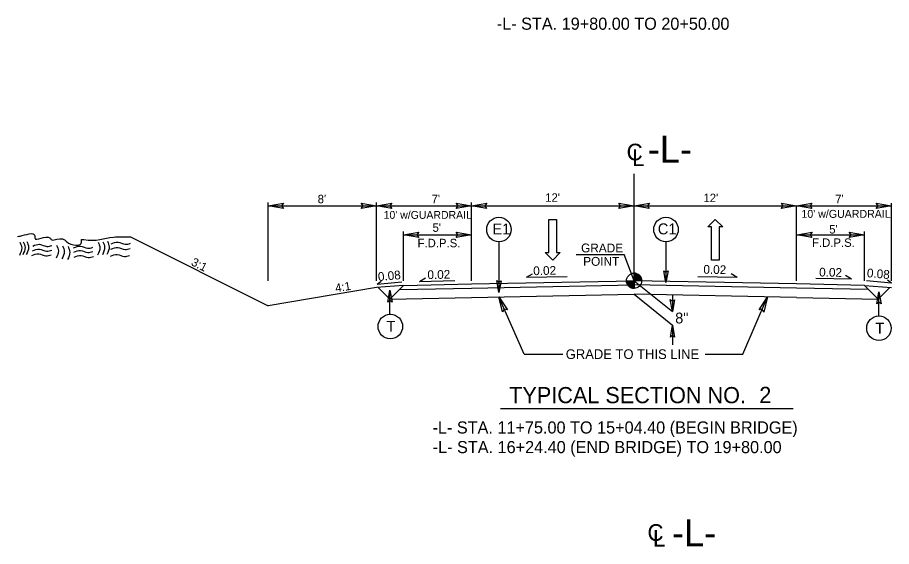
# Model space of a CAD drawing. Extents: x 1733676 to 1734289, y 540979 to 541226.
# Drawn here: x 1734171.6 to 1734236.1, y 541147.3 to 541186.4 of the extents above; entities that cross this region are included whole.
import ezdxf

# ---------------------------------------------------------------- set-up
doc = ezdxf.new("R2010")
doc.units = 0
for name, color, linetype in [('Old_Level_2', 7, 'Continuous'), ('Prop Dimension', 7, 'Continuous'), ('Prop Lane Arrow CELL', 7, 'Continuous'), ('Prop Terminator CELL', 7, 'Continuous'), ('Typical Grade Point Symbol CELL', 7, 'Continuous'), ('Typical ID Circle CELL', 7, 'Continuous'), ('Typical Pavement Slope CELL', 7, 'Continuous'), ('Typical Pavement Slope Information CELL', 7, 'Continuous'), ('Typical Shoulder Slope CELL', 7, 'Continuous'), ('Typical Shoulder Slope Information CELL', 7, 'Continuous'), ('Typical Slope Point Local CELL', 7, 'Continuous'), ('Typical Terminator CELL', 7, 'Continuous'), ('Typical Text Centerline CELL', 7, 'Continuous'), ('Typical Text General CELL', 7, 'Continuous'), ('Typical Text Grade Point CELL', 7, 'Continuous'), ('Typical Text ID Circle CELL', 7, 'Continuous'), ('Typical Text Label CELL', 7, 'Continuous')]:
    doc.layers.add(name, color=color, linetype=linetype)

msp = doc.modelspace()

# ---------------------------------------------------------------- linework, layer by layer
at = {"layer": 'Old_Level_2'}
for points in [[(1734171.638, 541170.263), (1734171.824, 541170.285), (1734172.92, 541170.298), (1734172.922, 541170.141), (1734174.019, 541170.154), (1734174.177, 541169.999), (1734174.334, 541170.001), (1734175.117, 541170.01), (1734175.275, 541169.855), (1734176.372, 541169.868), (1734176.37, 541170.024), (1734176.526, 541170.026), (1734178.717, 541170.208), (1734179.966, 541170.223)], [(1734171.821, 541169.824), (1734171.948, 541169.404), (1734171.779, 541168.858)], [(1734172.066, 541169.862), (1734172.194, 541169.442), (1734172.024, 541168.896)], [(1734172.329, 541169.882), (1734172.456, 541169.463), (1734172.287, 541168.917)], [(1734172.763, 541169.545), (1734173.27, 541169.674), (1734173.798, 541169.522), (1734174.183, 541169.597)], [(1734177.593, 541169.838), (1734177.72, 541169.418), (1734177.551, 541168.872)], [(1734177.943, 541169.86), (1734178.071, 541169.44), (1734177.902, 541168.894)], [(1734178.276, 541169.898), (1734178.404, 541169.479), (1734178.235, 541168.933)], [(1734178.551, 541169.7), (1734179.058, 541169.829), (1734179.586, 541169.677), (1734179.971, 541169.751)], [(1734172.749, 541169.194), (1734173.257, 541169.323), (1734173.785, 541169.171), (1734174.17, 541169.245)], [(1734174.525, 541169.609), (1734174.653, 541169.19), (1734174.484, 541168.644)], [(1734174.964, 541169.562), (1734175.092, 541169.142), (1734174.923, 541168.596)], [(1734175.368, 541169.514), (1734175.496, 541169.094), (1734175.327, 541168.548)], [(1734175.782, 541169.405), (1734176.289, 541169.533), (1734176.817, 541169.381), (1734177.203, 541169.456)], [(1734175.786, 541169.089), (1734176.293, 541169.217), (1734176.821, 541169.066), (1734177.206, 541169.14)], [(1734178.538, 541169.314), (1734179.045, 541169.442), (1734179.573, 541169.29), (1734179.958, 541169.365)], [(1734172.701, 541168.843), (1734173.208, 541168.971), (1734173.736, 541168.819), (1734174.121, 541168.894)], [(1734175.825, 541168.721), (1734176.332, 541168.849), (1734176.86, 541168.698), (1734177.246, 541168.772)], [(1734178.491, 541168.804), (1734178.998, 541168.933), (1734179.526, 541168.781), (1734179.912, 541168.856)]]:
    msp.add_spline(points, degree=3, dxfattribs=at)
at = {"layer": 'Prop Dimension'}
for p, q in [((1734217.135, 541166.983), (1734217.135, 541174.87)), ((1734190.135, 541166.983), (1734190.135, 541172.762)), ((1734190.135, 541172.512), (1734198.135, 541172.512)), ((1734198.135, 541166.983), (1734198.135, 541172.762)), ((1734198.135, 541172.512), (1734205.135, 541172.512)), ((1734205.135, 541166.983), (1734205.135, 541172.762)), ((1734205.135, 541172.512), (1734217.135, 541172.512)), ((1734217.135, 541172.512), (1734229.135, 541172.512)), ((1734229.135, 541166.983), (1734229.135, 541172.525)), ((1734229.135, 541172.512), (1734236.135, 541172.512)), ((1734236.135, 541166.983), (1734236.135, 541172.715)), ((1734200.13, 541166.983), (1734200.13, 541170.621)), ((1734200.13, 541170.371), (1734205.13, 541170.371)), ((1734229.139, 541170.371), (1734234.139, 541170.371)), ((1734234.139, 541166.983), (1734234.139, 541170.621)), ((1734212.862, 541168.921), (1734216.4, 541168.921)), ((1734217.135, 541166.983), (1734216.4, 541168.921)), ((1734217.135, 541166.983), (1734219.968, 541164.701)), ((1734217.135, 541165.983), (1734219.968, 541163.701)), ((1734219.968, 541165.907), (1734219.968, 541164.701)), ((1734225.162, 541161.561), (1734226.989, 541165.786)), ((1734209.026, 541161.561), (1734207.148, 541165.783)), ((1734219.968, 541163.701), (1734219.968, 541162.248)), ((1734209.026, 541161.561), (1734211.885, 541161.561)), ((1734222.385, 541161.561), (1734225.162, 541161.561))]:
    msp.add_line(p, q, dxfattribs=at)
at = {"layer": 'Prop Lane Arrow CELL'}
for p, q in [((1734210.838, 541169.058), (1734210.838, 541171.508)), ((1734210.838, 541171.508), (1734211.416, 541171.508)), ((1734211.416, 541171.508), (1734211.416, 541169.058)), ((1734222.583, 541170.956), (1734223.126, 541171.507)), ((1734222.846, 541170.956), (1734222.583, 541170.956)), ((1734222.846, 541168.506), (1734222.846, 541170.956)), ((1734223.126, 541171.507), (1734223.686, 541170.956)), ((1734223.686, 541170.956), (1734223.423, 541170.956)), ((1734223.423, 541170.956), (1734223.423, 541168.506)), ((1734211.136, 541168.507), (1734210.576, 541169.058)), ((1734210.576, 541169.058), (1734210.838, 541169.058)), ((1734211.678, 541169.058), (1734211.136, 541168.507)), ((1734211.416, 541169.058), (1734211.678, 541169.058)), ((1734223.423, 541168.506), (1734222.846, 541168.506))]:
    msp.add_line(p, q, dxfattribs=at)
at = {"layer": 'Prop Terminator CELL'}
for points in [[(1734191.26, 541172.318), (1734190.135, 541172.512), (1734191.266, 541172.712), (1734191.122, 541172.512)], [(1734197.01, 541172.706), (1734198.135, 541172.512), (1734197.003, 541172.312), (1734197.147, 541172.512)], [(1734199.26, 541172.318), (1734198.135, 541172.512), (1734199.266, 541172.712), (1734199.122, 541172.512)], [(1734204.01, 541172.706), (1734205.135, 541172.512), (1734204.003, 541172.312), (1734204.147, 541172.512)], [(1734206.26, 541172.318), (1734205.135, 541172.512), (1734206.266, 541172.712), (1734206.122, 541172.512)], [(1734216.01, 541172.706), (1734217.135, 541172.512), (1734216.003, 541172.312), (1734216.147, 541172.512)], [(1734218.26, 541172.318), (1734217.135, 541172.512), (1734218.266, 541172.712), (1734218.122, 541172.512)], [(1734228.01, 541172.706), (1734229.135, 541172.512), (1734228.003, 541172.312), (1734228.147, 541172.512)], [(1734230.26, 541172.318), (1734229.135, 541172.512), (1734230.266, 541172.712), (1734230.122, 541172.512)], [(1734235.01, 541172.706), (1734236.135, 541172.512), (1734235.003, 541172.312), (1734235.147, 541172.512)], [(1734201.255, 541170.177), (1734200.13, 541170.371), (1734201.262, 541170.571), (1734201.118, 541170.371)], [(1734204.005, 541170.565), (1734205.13, 541170.371), (1734203.999, 541170.171), (1734204.143, 541170.371)], [(1734230.264, 541170.177), (1734229.139, 541170.371), (1734230.27, 541170.571), (1734230.127, 541170.371)], [(1734233.014, 541170.565), (1734234.139, 541170.371), (1734233.008, 541170.171), (1734233.152, 541170.371)], [(1734226.365, 541164.83), (1734226.989, 541165.786), (1734226.724, 541164.668), (1734226.597, 541164.879)], [(1734207.428, 541164.677), (1734207.148, 541165.783), (1734207.79, 541164.831), (1734207.549, 541164.881)]]:
    msp.add_lwpolyline(points, close=True, dxfattribs=at)
at = {"layer": 'Typical Grade Point Symbol CELL'}
for p, q in [((1734217.135, 541166.983), (1734217.135, 541167.543)), ((1734216.575, 541166.983), (1734217.135, 541166.983)), ((1734217.133, 541166.424), (1734217.135, 541166.983)), ((1734217.135, 541166.983), (1734217.133, 541166.424)), ((1734217.694, 541166.983), (1734217.135, 541166.983))]:
    msp.add_line(p, q, dxfattribs=at)
for points in [[(1734217.14, 541167.543), (1734217.14, 541167.543), (1734217.14, 541166.983)], [(1734217.151, 541167.543), (1734217.151, 541166.983)], [(1734217.162, 541167.541), (1734217.162, 541166.983)], [(1734217.173, 541167.541), (1734217.173, 541166.983)], [(1734217.184, 541167.54), (1734217.184, 541166.983)], [(1734217.196, 541167.539), (1734217.196, 541166.983)], [(1734217.207, 541167.538), (1734217.207, 541166.983)], [(1734217.218, 541167.536), (1734217.218, 541166.983)], [(1734217.229, 541167.535), (1734217.229, 541166.983)], [(1734217.24, 541167.533), (1734217.24, 541166.983)], [(1734217.252, 541167.53), (1734217.252, 541166.983)], [(1734217.263, 541167.528), (1734217.263, 541166.983)], [(1734217.274, 541167.525), (1734217.274, 541166.983)], [(1734217.285, 541167.522), (1734217.285, 541166.983)], [(1734217.296, 541167.519), (1734217.296, 541166.983)], [(1734217.308, 541167.515), (1734217.308, 541166.983)], [(1734217.319, 541167.512), (1734217.319, 541166.983)], [(1734217.33, 541167.508), (1734217.33, 541166.983)], [(1734217.341, 541167.503), (1734217.341, 541166.983)], [(1734217.352, 541167.498), (1734217.352, 541166.983)], [(1734217.364, 541167.493), (1734217.364, 541166.983)], [(1734217.375, 541167.488), (1734217.375, 541166.983)], [(1734217.386, 541167.483), (1734217.386, 541166.983)], [(1734217.397, 541167.477), (1734217.397, 541166.983)], [(1734217.408, 541167.471), (1734217.408, 541166.983)], [(1734217.419, 541167.464), (1734217.419, 541166.983)], [(1734217.431, 541167.458), (1734217.431, 541166.983)], [(1734217.442, 541167.451), (1734217.442, 541166.983)], [(1734217.453, 541167.443), (1734217.453, 541166.983)], [(1734217.464, 541167.435), (1734217.464, 541166.983)], [(1734217.475, 541167.427), (1734217.475, 541166.983)], [(1734217.487, 541167.418), (1734217.487, 541166.983)], [(1734217.498, 541167.408), (1734217.498, 541166.983)], [(1734217.509, 541167.398), (1734217.509, 541166.983)], [(1734217.52, 541167.388), (1734217.52, 541166.983)], [(1734217.531, 541167.377), (1734217.531, 541166.983)], [(1734217.543, 541167.366), (1734217.543, 541166.983)], [(1734217.554, 541167.354), (1734217.554, 541166.983)], [(1734217.565, 541167.34), (1734217.565, 541166.983)], [(1734217.576, 541167.326), (1734217.576, 541166.983)], [(1734217.587, 541167.311), (1734217.587, 541166.983)], [(1734217.599, 541167.295), (1734217.599, 541166.983)], [(1734217.61, 541167.278), (1734217.61, 541166.983)], [(1734217.621, 541167.259), (1734217.621, 541166.983)], [(1734217.632, 541167.239), (1734217.632, 541166.983)], [(1734217.643, 541167.216), (1734217.643, 541166.983)], [(1734217.654, 541167.19), (1734217.654, 541166.983)], [(1734217.666, 541167.158), (1734217.666, 541166.983)], [(1734217.677, 541167.12), (1734217.677, 541166.983)], [(1734216.578, 541166.983), (1734216.578, 541166.922)], [(1734216.589, 541166.983), (1734216.589, 541166.856)], [(1734216.6, 541166.983), (1734216.6, 541166.817)], [(1734216.611, 541166.983), (1734216.611, 541166.783)], [(1734216.623, 541166.983), (1734216.623, 541166.757)], [(1734216.634, 541166.983), (1734216.634, 541166.733)], [(1734216.645, 541166.983), (1734216.645, 541166.712)], [(1734216.656, 541166.983), (1734216.656, 541166.692)], [(1734216.667, 541166.983), (1734216.667, 541166.675)], [(1734216.678, 541166.983), (1734216.678, 541166.659)], [(1734216.69, 541166.983), (1734216.69, 541166.644)], [(1734216.701, 541166.983), (1734216.701, 541166.63)], [(1734216.712, 541166.983), (1734216.712, 541166.616)], [(1734216.723, 541166.983), (1734216.723, 541166.604)], [(1734216.734, 541166.983), (1734216.734, 541166.592)], [(1734216.746, 541166.983), (1734216.746, 541166.58)], [(1734216.757, 541166.983), (1734216.757, 541166.57)], [(1734216.768, 541166.983), (1734216.768, 541166.56)], [(1734216.779, 541166.983), (1734216.779, 541166.551)], [(1734216.79, 541166.983), (1734216.79, 541166.542)], [(1734216.802, 541166.983), (1734216.802, 541166.533)], [(1734216.813, 541166.983), (1734216.813, 541166.526)], [(1734216.824, 541166.983), (1734216.824, 541166.518)], [(1734216.835, 541166.983), (1734216.835, 541166.511)], [(1734216.846, 541166.983), (1734216.846, 541166.503)], [(1734216.857, 541166.983), (1734216.857, 541166.497)], [(1734216.869, 541166.983), (1734216.869, 541166.491)], [(1734216.88, 541166.983), (1734216.88, 541166.485)], [(1734216.891, 541166.983), (1734216.891, 541166.48)], [(1734216.902, 541166.983), (1734216.902, 541166.475)], [(1734216.913, 541166.983), (1734216.913, 541166.47)], [(1734216.925, 541166.983), (1734216.925, 541166.465)], [(1734216.936, 541166.983), (1734216.936, 541166.46)], [(1734216.947, 541166.983), (1734216.947, 541166.456)], [(1734216.958, 541166.983), (1734216.958, 541166.452)], [(1734216.969, 541166.983), (1734216.969, 541166.449)], [(1734216.981, 541166.983), (1734216.981, 541166.446)], [(1734216.992, 541166.983), (1734216.992, 541166.442)], [(1734217.003, 541166.983), (1734217.003, 541166.44)], [(1734217.014, 541166.983), (1734217.014, 541166.437)], [(1734217.025, 541166.983), (1734217.025, 541166.435)], [(1734217.036, 541166.983), (1734217.036, 541166.432)], [(1734217.048, 541166.983), (1734217.048, 541166.431)], [(1734217.059, 541166.983), (1734217.059, 541166.429)], [(1734217.07, 541166.983), (1734217.07, 541166.427)], [(1734217.081, 541166.983), (1734217.081, 541166.426)], [(1734217.092, 541166.983), (1734217.092, 541166.425)], [(1734217.104, 541166.983), (1734217.104, 541166.425)], [(1734217.115, 541166.983), (1734217.115, 541166.424)], [(1734217.126, 541166.983), (1734217.126, 541166.424), (1734217.126, 541166.424)], [(1734217.688, 541167.063), (1734217.688, 541166.983)]]:
    msp.add_lwpolyline(points, dxfattribs=at)
msp.add_circle((1734217.134, 541166.983), 0.559, dxfattribs=at)
for start, end in [(359.99048, 89.99048), (179.99048, 269.99048)]:
    msp.add_arc((1734217.134, 541166.983), 0.559, start, end, dxfattribs=at)
at = {"layer": 'Typical ID Circle CELL'}
for p, q in [((1734207.168, 541169.861), (1734207.168, 541166.109)), ((1734219.493, 541169.861), (1734219.493, 541166.841)), ((1734199.12, 541164.507), (1734199.12, 541166.286)), ((1734235.208, 541164.384), (1734235.208, 541166.163))]:
    msp.add_line(p, q, dxfattribs=at)
for centre in [(1734207.168, 541170.767), (1734219.493, 541170.767), (1734199.152, 541163.601), (1734235.208, 541163.477)]:
    msp.add_circle(centre, 0.906, dxfattribs=at)
at = {"layer": 'Typical Pavement Slope CELL'}
for p, q in [((1734200.13, 541166.641), (1734198.13, 541166.474)), ((1734205.135, 541166.743), (1734217.135, 541166.983)), ((1734205.135, 541166.443), (1734217.141, 541166.683)), ((1734229.135, 541166.443), (1734217.129, 541166.683)), ((1734229.135, 541166.743), (1734217.135, 541166.983)), ((1734234.139, 541166.641), (1734236.14, 541166.474)), ((1734205.135, 541165.743), (1734217.135, 541165.983)), ((1734229.135, 541165.743), (1734217.135, 541165.983)), ((1734199.112, 541165.623), (1734205.135, 541165.743)), ((1734229.135, 541165.743), (1734235.157, 541165.623))]:
    msp.add_line(p, q, dxfattribs=at)
at = {"layer": 'Typical Pavement Slope Information CELL'}
for p, q in [((1734201.309, 541166.939), (1734201.747, 541167.203)), ((1734209.202, 541167.239), (1734209.639, 541167.504)), ((1734209.202, 541167.239), (1734212.193, 541167.299)), ((1734224.745, 541167.218), (1734221.851, 541167.276)), ((1734224.745, 541167.218), (1734224.296, 541167.49)), ((1734233.182, 541167.095), (1734230.542, 541167.148)), ((1734233.182, 541167.095), (1734232.733, 541167.366)), ((1734198.19, 541166.735), (1734198.482, 541166.94)), ((1734198.19, 541166.735), (1734199.999, 541166.896)), ((1734201.309, 541166.939), (1734203.909, 541166.991)), ((1734236.132, 541166.81), (1734234.294, 541166.965)), ((1734236.132, 541166.81), (1734235.831, 541167.019))]:
    msp.add_line(p, q, dxfattribs=at)
at = {"layer": 'Typical Shoulder Slope CELL'}
for p, q in [((1734198.25, 541166.484), (1734199.112, 541165.622)), ((1734200.13, 541166.641), (1734199.112, 541165.622)), ((1734199.824, 541166.334), (1734205.141, 541166.443)), ((1734200.13, 541166.641), (1734205.135, 541166.743)), ((1734234.445, 541166.334), (1734229.129, 541166.443)), ((1734234.139, 541166.641), (1734229.135, 541166.743)), ((1734234.139, 541166.641), (1734235.158, 541165.622)), ((1734236.02, 541166.484), (1734235.158, 541165.622))]:
    msp.add_line(p, q, dxfattribs=at)
at = {"layer": 'Typical Slope Point Local CELL'}
for p in [(1734179.966, 541170.223), (1734198.13, 541166.474)]:
    msp.add_line(p, (1734190.13, 541165.141), dxfattribs=at)
at = {"layer": 'Typical Terminator CELL'}
for points in [[(1734219.644, 541167.72), (1734219.493, 541166.841), (1734219.337, 541167.724), (1734219.493, 541167.612)], [(1734207.32, 541166.988), (1734207.168, 541166.109), (1734207.012, 541166.993), (1734207.168, 541166.88)], [(1734198.969, 541165.407), (1734199.12, 541166.286), (1734199.276, 541165.403), (1734199.12, 541165.515)], [(1734235.056, 541165.284), (1734235.208, 541166.163), (1734235.364, 541165.28), (1734235.208, 541165.392)], [(1734220.119, 541165.58), (1734219.968, 541164.701), (1734219.812, 541165.585), (1734219.968, 541165.472)], [(1734219.816, 541162.822), (1734219.968, 541163.701), (1734220.124, 541162.817), (1734219.968, 541162.929)]]:
    msp.add_lwpolyline(points, close=True, dxfattribs=at)
at = {"layer": 'Typical Text Label CELL'}
msp.add_line((1734207.283, 541157.537), (1734228.888, 541157.537), dxfattribs=at)

# ---------------------------------------------------------------- texts
at = {"layer": 'Typical Pavement Slope Information CELL'}
for rotation, p in [(1.14574, (1734209.703, 541167.394)), (358.85426, (1734222.248, 541167.503))]:
    msp.add_text('0.02', height=0.6476, rotation=rotation, dxfattribs=at).set_placement(p)
at = {"layer": 'Typical Shoulder Slope Information CELL'}
for s, rotation, p in [('0.08', 5.10489, (1734198.265, 541166.954)), ('0.02', 1.14574, (1734201.894, 541167.103)), ('0.02', 358.85426, (1734230.791, 541167.301)), ('0.08', 355.18719, (1734234.298, 541167.25))]:
    msp.add_text(s, height=0.6476, rotation=rotation, dxfattribs=at).set_placement(p)
at = {"layer": 'Typical Slope Point Local CELL'}
for s, height, rotation, p in [("8'", 0.6249, 360, (1734193.789, 541172.708)), ("7'", 0.6249, 360, (1734202.196, 541172.708)), ("12'", 0.6249, 360, (1734210.581, 541172.817)), ("12'", 0.6249, 360, (1734222.255, 541172.79)), ("7'", 0.6249, 360, (1734231.982, 541172.713)), ("10' w/GUARDRAIL", 0.58491, 360, (1734229.489, 541171.63)), ("10' w/GUARDRAIL", 0.57868, 360, (1734198.656, 541171.557)), ("5'", 0.6249, 360, (1734202.264, 541170.597)), ("5'", 0.6249, 360, (1734231.539, 541170.471)), ('F.D.P.S.', 0.6249, 360, (1734201.161, 541169.454)), ('F.D.P.S.', 0.6249, 360, (1734230.272, 541169.487)), ('3:1', 0.6249, 333.43495, (1734184.401, 541168.159)), ('4:1', 0.6249, 9.46232, (1734195.135, 541166.125)), ('8"', 0.8, 360, (1734220.172, 541163.828))]:
    msp.add_text(s, height=height, rotation=rotation, dxfattribs=at).set_placement(p)
at = {"layer": 'Typical Text Centerline CELL'}
for s, height, p in [('-L-', 2, (1734218.148, 541175.705)), ('C', 1.23, (1734216.586, 541175.875)), ('C', 1.23, (1734218.124, 541147.768)), ('-L-', 2, (1734219.93, 541147.367))]:
    msp.add_text(s, height=height, dxfattribs=at).set_placement(p)
for p in [(1734216.995, 541175.455), (1734218.533, 541147.348)]:
    msp.add_text('L', height=1.231, rotation=359.9469, dxfattribs=at).set_placement(p)
at = {"layer": 'Typical Text General CELL'}
msp.add_text('GRADE TO THIS LINE', height=0.71614, dxfattribs=at).set_placement((1734212.096, 541161.203))
at = {"layer": 'Typical Text Grade Point CELL'}
for s, p in [('GRADE', (1734213.226, 541169.077)), ('POINT', (1734213.383, 541168.088))]:
    msp.add_text(s, height=0.6525, dxfattribs=at).set_placement(p)
at = {"layer": 'Typical Text ID Circle CELL'}
for s, height, p in [('E1', 0.8112, (1734206.678, 541170.4)), ('C1', 0.8112, (1734218.888, 541170.408)), ('T', 0.811, (1734198.86, 541163.21)), ('T', 0.811, (1734234.941, 541163.072))]:
    msp.add_text(s, height=height, dxfattribs=at).set_placement(p)
at = {"layer": 'Typical Text Label CELL'}
for s, height, p in [('-L- STA. 19+80.00 TO 20+50.00', 0.89517, (1734207.007, 541185.524)), ('TYPICAL SECTION NO.  ', 1.19356, (1734207.924, 541157.937)), ('2', 1.194, (1734226.376, 541157.953)), ('-L- STA. 11+75.00 TO 15+04.40 (BEGIN BRIDGE)', 0.89517, (1734202.265, 541155.697)), ('-L- STA. 16+24.40 (END BRIDGE) TO 19+80.00', 0.89517, (1734202.278, 541154.246))]:
    msp.add_text(s, height=height, dxfattribs=at).set_placement(p)

doc.saveas('drawing.dxf')
